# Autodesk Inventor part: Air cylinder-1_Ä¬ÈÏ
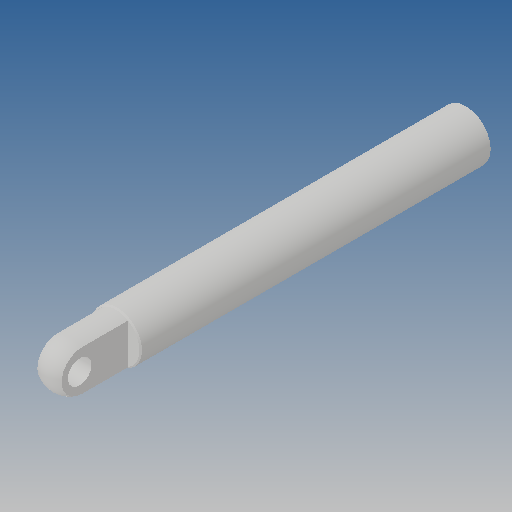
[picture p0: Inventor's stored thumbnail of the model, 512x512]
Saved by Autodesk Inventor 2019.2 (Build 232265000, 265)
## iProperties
Created: 2010-06
Part Number: Air cylinder-1_Ä¬ÈÏ
Material: Ogólny
Document SubType Name: Modeling
Designer: CADENGINEERING4
Density: 1 g/cm^3
Appearance: Domyślna
Author: CADENGINEERING4
Revision Number: ÈÎºÎ
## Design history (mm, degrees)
feature "NONE"
node "Bryła1"
